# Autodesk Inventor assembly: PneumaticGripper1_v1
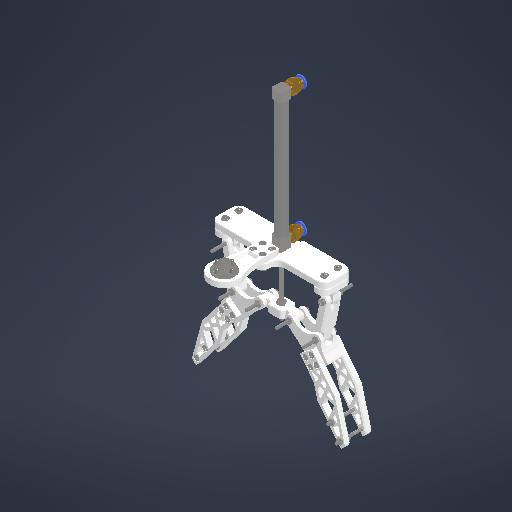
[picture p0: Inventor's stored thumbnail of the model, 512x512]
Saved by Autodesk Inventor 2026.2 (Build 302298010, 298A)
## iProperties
Created: 2026-05
Part Number: PneumaticGripper1_v1
Document SubType Name: Assembly
Designer: work
Author: work
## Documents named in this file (16)
- C:\Users\work\Desktop\ARD_v1\ARD_hardware\PneumaticGripper_v1\PneumaticGripper1_v1.iam
- C:\Users\work\Desktop\ARD_v1\ARD_hardware\PneumaticGripper_v1\Pneumatic fitting\CDJ2B10_100\CDJ2B10.iam
- C:\Users\work\Desktop\ARD_v1\ARD_hardware\PneumaticGripper_v1\Cylinder fixing parts.ipt
- C:\Users\work\Desktop\ARD_v1\ARD_hardware\PneumaticGripper_v1\rod-fixing parts.ipt
- C:\Users\work\Desktop\ARD_v1\ARD_hardware\PneumaticGripper_v1\Pneumatic fitting\CDJ2B10_100\Rod.ipt
- C:\Users\work\Desktop\ARD_v1\ARD_hardware\PneumaticGripper_v1\Pneumatic fitting\CDJ2B10_100\AS 1474 - M4(1).ipt
- C:\Users\work\Desktop\ARD_v1\ARD_hardware\PneumaticGripper_v1\Bottom Link Parts.ipt
- C:\Users\work\Desktop\ARD_v1\ARD_hardware\PneumaticGripper_v1\Link Support Parts.ipt
- C:\Users\work\Desktop\ARD_v1\ARD_hardware\PneumaticGripper_v1\Link Parts.ipt
- C:\Users\work\Desktop\ARD_v1\ARD_hardware\PneumaticGripper_v1\Tongs_R.ipt
- C:\Users\work\Desktop\ARD_v1\ARD_hardware\PneumaticGripper_v1\Tongs_l.ipt
- C:\Users\work\Desktop\ARD_v1\ARD_hardware\PneumaticGripper_v1\ovject\KS B 1003 - M 3 x 12.ipt
- C:\Users\work\Desktop\ARD_v1\ARD_hardware\PneumaticGripper_v1\ovject\KS B 1003 - M 3 x 30.ipt
- C:\Users\work\Desktop\ARD_v1\ARD_hardware\PneumaticGripper_v1\ovject\JIS B 1181 - A_B M3.ipt
- C:\Users\work\Desktop\ARD_v1\ARD_hardware\PneumaticGripper_v1\Flange Bracket.ipt
- C:\Users\work\Desktop\ARD_v1\ARD_hardware\PneumaticGripper_v1\ovject\flange joint 16pi (5 to 3).ipt
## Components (81 placed, 15 different names)
1. CDJ2B10:1 [sub-assembly] — 각도:1
2. Cylinder fixing parts:1
3. rod-fixing parts:1
4. Rod:1 — 플러쉬:1
5. Flange Bracket:1
6. AS 1474 - M4(1):1 — 각도:2, 플러쉬:1
7. AS 1474 - M4(1):2 — 각도:3
8. Bottom Link Parts:1
9. Bottom Link Parts:2
10. Link Support Parts:1
11. Link Support Parts:2
12. Link Parts:1
13. Link Parts:3
14. Tongs_R:1
15. Tongs_l:1
16. Tongs_R:3
17. Tongs_l:2
18. JIS B 1181 - A_B M3:18
19. JIS B 1181 - A_B M3:19
20. JIS B 1181 - A_B M3:20
21. JIS B 1181 - A_B M3:21
22. JIS B 1181 - A_B M3:22
23. JIS B 1181 - A_B M3:23
24. JIS B 1181 - A_B M3:24
25. JIS B 1181 - A_B M3:25
26. KS B 1003 - M 3 x 12:22
27. KS B 1003 - M 3 x 12:23
28. KS B 1003 - M 3 x 12:24
29. KS B 1003 - M 3 x 12:25
30. KS B 1003 - M 3 x 12:26
31. KS B 1003 - M 3 x 12:27
32. KS B 1003 - M 3 x 12:28
33. KS B 1003 - M 3 x 12:29
34. KS B 1003 - M 3 x 12:1
35. KS B 1003 - M 3 x 12:2
36. KS B 1003 - M 3 x 12:3
37. KS B 1003 - M 3 x 12:4
38. KS B 1003 - M 3 x 12:5
39. KS B 1003 - M 3 x 12:6
40. KS B 1003 - M 3 x 12:7
41. KS B 1003 - M 3 x 12:8
42. KS B 1003 - M 3 x 12:9
43. KS B 1003 - M 3 x 12:11
44. KS B 1003 - M 3 x 12:12
45. KS B 1003 - M 3 x 12:13
46. KS B 1003 - M 3 x 12:14
47. KS B 1003 - M 3 x 12:15
48. KS B 1003 - M 3 x 12:16
49. KS B 1003 - M 3 x 12:17
50. KS B 1003 - M 3 x 12:18
51. KS B 1003 - M 3 x 12:19
52. KS B 1003 - M 3 x 12:20
53. KS B 1003 - M 3 x 12:21
54. KS B 1003 - M 3 x 30:1
55. KS B 1003 - M 3 x 30:2
56. KS B 1003 - M 3 x 30:3
57. flange joint 16pi (5 to 3):1
58. KS B 1003 - M 3 x 30:4
59. KS B 1003 - M 3 x 30:5
60. KS B 1003 - M 3 x 30:6
61. KS B 1003 - M 3 x 30:7
62. KS B 1003 - M 3 x 30:8
63. KS B 1003 - M 3 x 30:9
64. KS B 1003 - M 3 x 30:10
65. JIS B 1181 - A_B M3:1
66. JIS B 1181 - A_B M3:2
67. JIS B 1181 - A_B M3:3
68. JIS B 1181 - A_B M3:4
69. JIS B 1181 - A_B M3:5
70. JIS B 1181 - A_B M3:6
71. JIS B 1181 - A_B M3:7
72. JIS B 1181 - A_B M3:8
73. JIS B 1181 - A_B M3:9
74. JIS B 1181 - A_B M3:10
75. JIS B 1181 - A_B M3:11
76. JIS B 1181 - A_B M3:12
77. JIS B 1181 - A_B M3:13
78. JIS B 1181 - A_B M3:14
79. JIS B 1181 - A_B M3:15
80. JIS B 1181 - A_B M3:16
81. JIS B 1181 - A_B M3:17
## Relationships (4: Angle 3, Flush 1)
- 각도:1 [Angle]: CDJ2B10:1
- 각도:2 [Angle]: AS 1474 - M4(1):1
- 각도:3 [Angle]: AS 1474 - M4(1):2
- 플러쉬:1 [Flush]: Rod:1 ↔ AS 1474 - M4(1):1
